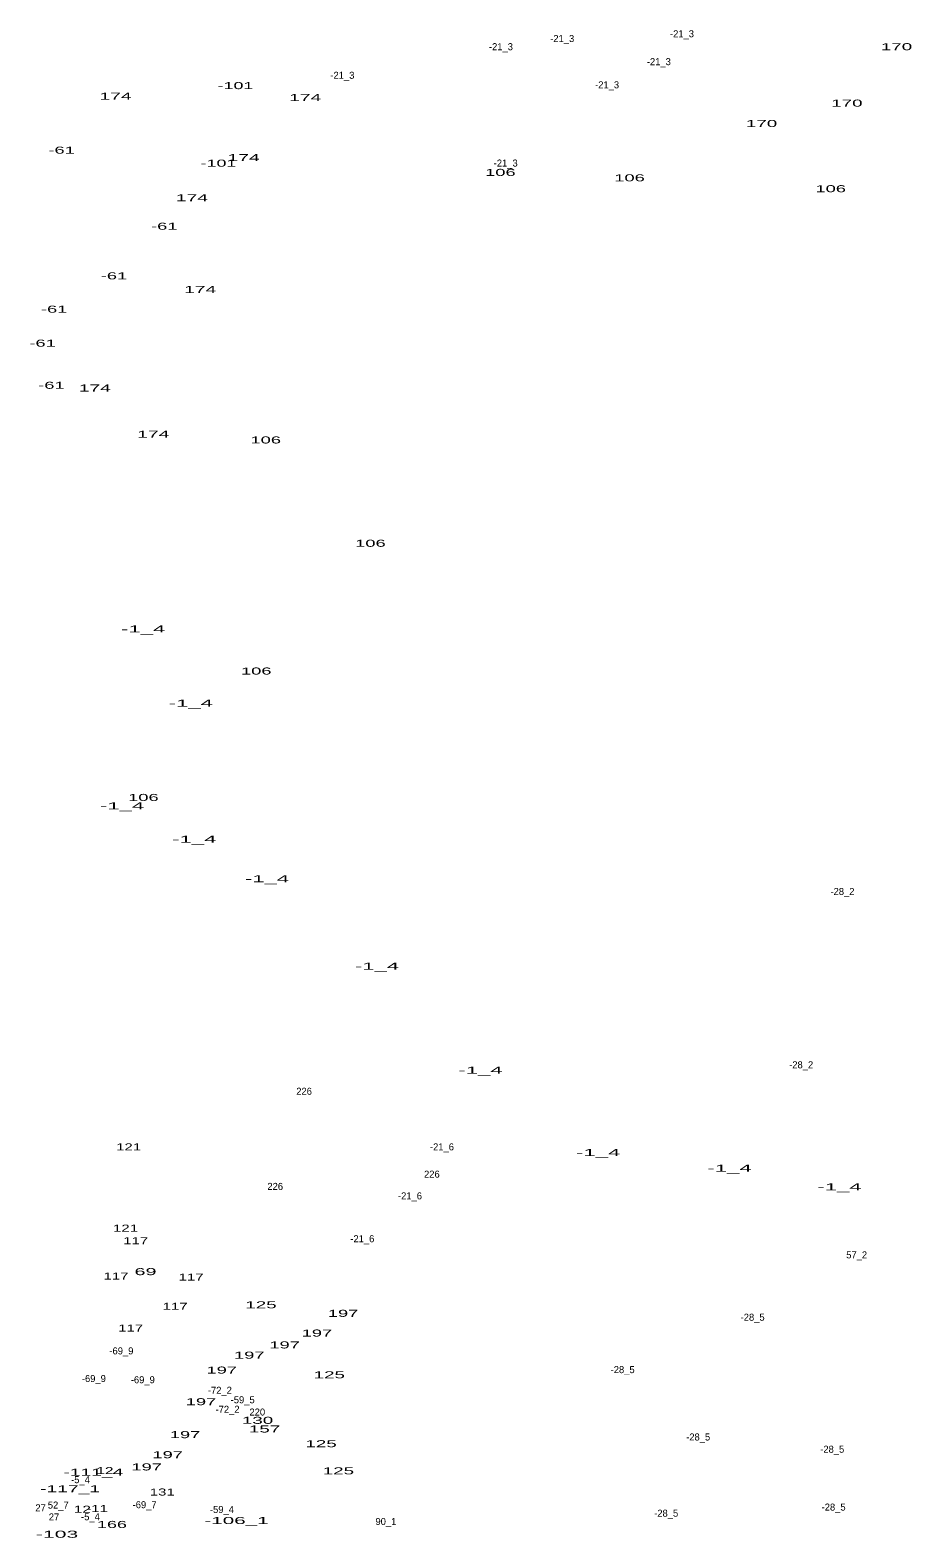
# Model space of a CAD drawing. Extents: x -656096 to -652763, y -1002270 to -998958.
# Drawn here: x -654559 to -654064, y -1000713 to -999854 of the extents above; entities that cross this region are included whole.
import ezdxf
from ezdxf.enums import TextEntityAlignment as Align

# ---------------------------------------------------------------- set-up
doc = ezdxf.new("R2010")
doc.units = 0
doc.header["$LTSCALE"] = 1.6
doc.layers.add('24', color=7, linetype='Continuous')

msp = doc.modelspace()

# ---------------------------------------------------------------- texts
at = {"layer": '24'}
for s, p in [('-21_3', (-654255.896, -999860.77)), ('-21_3', (-654187.656, -999858.06)), ('-21_3', (-654290.796, -999865.43)), ('-21_3', (-654200.836, -999873.96)), ('-21_3', (-654381.136, -999881.72)), ('-21_3', (-654230.306, -999887.15)), ('-21_3', (-654288.076, -999931.76)), ('-28_2', (-654096.202, -1000346.99)), ('-28_2', (-654119.742, -1000445.79)), ('226', (-654402.953, -1000460.89)), ('-21_6', (-654324.402, -1000492.59)), ('226', (-654330.153, -1000508.14)), ('226', (-654419.403, -1000515.12)), ('-21_6', (-654342.622, -1000520.52)), ('-21_6', (-654369.762, -1000544.95)), ('57_2', (-654088.13, -1000554.16)), ('-28_5', (-654147.402, -1000589.71)), ('-69_9', (-654507.038, -1000608.9)), ('-28_5', (-654221.462, -1000619.57)), ('-69_9', (-654522.728, -1000624.66)), ('-69_9', (-654494.848, -1000625.34)), ('-72_2', (-654450.928, -1000631.34)), ('-59_5', (-654437.948, -1000636.75)), ('-72_2', (-654446.568, -1000642.19)), ('220', (-654429.621, -1000643.75)), ('-28_5', (-654178.422, -1000657.97)), ('-28_5', (-654102.032, -1000664.96)), ('-5_4', (-654530.338, -1000682.3)), ('52_7', (-654543.02, -1000696.78)), ('-69_7', (-654493.808, -1000696.57)), ('-28_5', (-654101.262, -1000697.93)), ('27', (-654553.093, -1000698.33)), ('27', (-654545.443, -1000703.56)), ('-5_4', (-654524.668, -1000703.42)), ('-5_4', (-654524.668, -1000703.42)), ('-59_4', (-654449.752, -1000699.29)), ('90_1', (-654356.338, -1000706.13)), ('-28_5', (-654196.642, -1000701.42))]:
    msp.add_text(s, height=4, dxfattribs=at).set_placement(p, align=Align.CENTER)
for s, width, p in [('170', 2, (-654065.429, -999865.43)), ('-101', 1.9, (-654442.033, -999887.61)), ('174', 2.05, (-654510.388, -999893.63)), ('174', 2.05, (-654402.338, -999894.41)), ('170', 2, (-654093.699, -999897.58)), ('170', 2, (-654142.299, -999909.2)), ('-61', 1.95, (-654541.095, -999924.39)), ('-101', 1.9, (-654451.723, -999931.82)), ('174', 2.05, (-654437.388, -999928.66)), ('106', 1.95, (-654291.119, -999937.08)), ('106', 1.95, (-654217.539, -999940.18)), ('106', 1.95, (-654102.909, -999946.38)), ('174', 2.05, (-654466.818, -999951.52)), ('-61', 1.95, (-654482.625, -999967.78)), ('-61', 1.95, (-654511.275, -999996.06)), ('174', 2.05, (-654462.178, -1000003.82)), ('-61', 1.95, (-654545.355, -1000015.05)), ('-61', 1.95, (-654551.945, -1000034.42)), ('-61', 1.95, (-654546.905, -1000058.44)), ('174', 2.05, (-654522.198, -1000059.99)), ('174', 2.05, (-654488.898, -1000086.34)), ('106', 1.95, (-654424.799, -1000089.61)), ('106', 1.95, (-654365.159, -1000148.5)), ('-1_4', 2.35, (-654494.627, -1000197.36)), ('106', 1.95, (-654430.219, -1000221.33)), ('-1_4', 2.35, (-654467.487, -1000239.63)), ('106', 1.95, (-654494.509, -1000293.39)), ('-1_4', 2.35, (-654506.647, -1000298.2)), ('-1_4', 2.35, (-654465.547, -1000317.21)), ('-1_4', 2.35, (-654424.057, -1000339.71)), ('-1_4', 2.35, (-654361.397, -1000389.55)), ('-1_4', 2.35, (-654302.467, -1000448.89)), ('121', 1.6, (-654502.934, -1000492.6)), ('-1_4', 2.35, (-654235.387, -1000495.83)), ('-1_4', 2.35, (-654160.557, -1000504.75)), ('-1_4', 2.35, (-654097.937, -1000515.41)), ('121', 1.6, (-654504.674, -1000538.9)), ('117', 1.6, (-654498.889, -1000546.07)), ('117', 1.6, (-654510.119, -1000566.22)), ('69', 2.1, (-654493.301, -1000563.71)), ('117', 1.6, (-654467.319, -1000566.8)), ('117', 1.6, (-654476.419, -1000583.46)), ('125', 2, (-654427.507, -1000582.61)), ('197', 1.95, (-654380.737, -1000587.48)), ('117', 1.6, (-654501.789, -1000595.85)), ('197', 1.95, (-654395.647, -1000598.72)), ('197', 1.95, (-654434.177, -1000611.31)), ('197', 1.95, (-654414.047, -1000605.5)), ('197', 1.95, (-654449.867, -1000619.83)), ('125', 2, (-654388.587, -1000622.51)), ('197', 1.95, (-654461.677, -1000637.85)), ('130', 2, (-654429.474, -1000648.47)), ('157', 2, (-654425.473, -1000653.41)), ('197', 1.95, (-654470.777, -1000656.64)), ('125', 2, (-654393.267, -1000661.79)), ('197', 1.95, (-654480.657, -1000668.07)), ('-111_4', 2.05, (-654523.039, -1000678.02)), ('12', 1.65, (-654516.427, -1000677.14)), ('197', 1.95, (-654492.657, -1000675.04)), ('125', 2, (-654383.397, -1000677.29)), ('-117_1', 2.05, (-654536.279, -1000687.48)), ('131', 1.6, (-654483.764, -1000689.34)), ('12', 1.65, (-654529.317, -1000699.15)), ('-11', 1.6, (-654520.907, -1000698.72)), ('-106_1', 2.2, (-654441.459, -1000705.6)), ('-103', 2.25, (-654543.717, -1000713.41)), ('166', 1.9, (-654512.407, -1000707.82))]:
    msp.add_text(s, height=4, dxfattribs=dict(at, width=width)).set_placement(p, align=Align.CENTER)

doc.saveas('drawing.dxf')
